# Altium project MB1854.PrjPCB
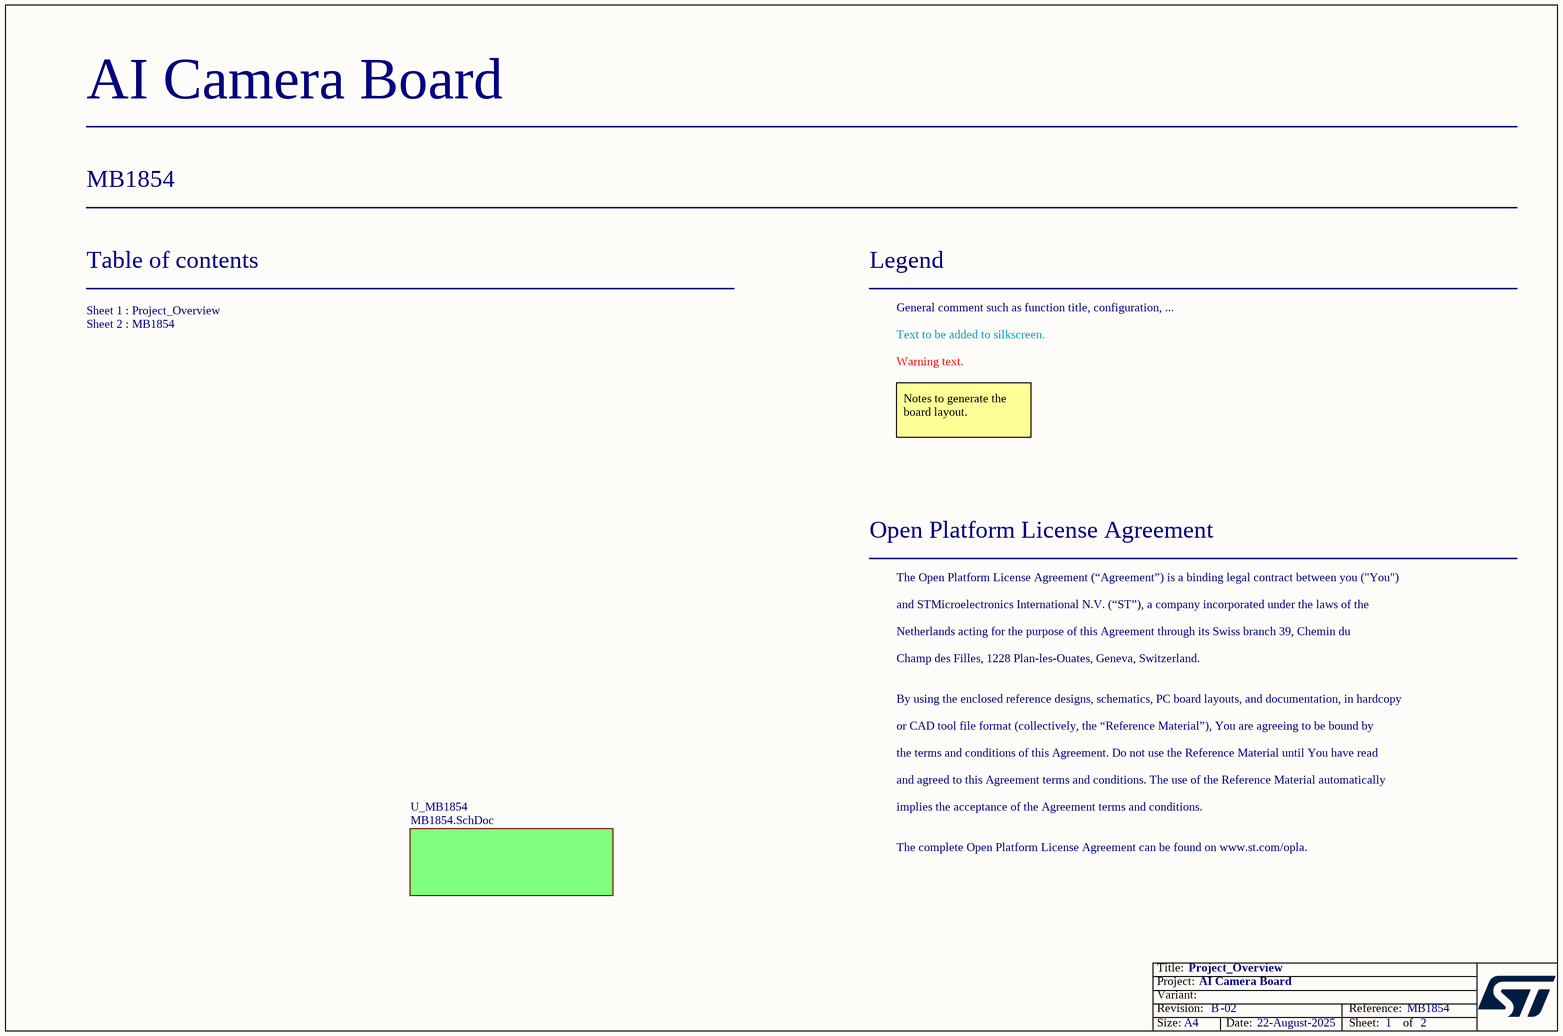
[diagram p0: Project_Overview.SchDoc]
Board_Assembly_Revision: 02; Board_Document_Date: 22-August-2025; Board_Name: AI Camera Board; Board_PCB_Revision: B; Board_Reference: MB1854
2 sheets, 45 parts. Net scope: global (net labels, ports and power ports of the same name join across sheets).
Board file: MB1854.PcbDoc
Sheets:
  Project_Overview.SchDoc
    U_MB1854 = MB1854.SchDoc

## Sheet Project_Overview.SchDoc: Project_Overview
size A4; Date: Not used; ApprovedBy: Not used; CheckedBy: Not used; Author: Not used; CompanyName: STMicroelectronics; DrawnBy: Not used; Engineer: Not used; Organization: Not used; Address1: Not used; Address2: Not used; Address3: Not used; Address4: Not used; DocumentNumber: 1; Revision: Not used; SheetNumber: 1; SheetTotal: 2

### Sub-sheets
U_MB1854 = MB1854.SchDoc: no entries

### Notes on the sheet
- Table of contents
- Legend
- General comment such as function title, configuration, ...
- Sheet 1 : Project_Overview
  Sheet 2 : MB1854
- Text to be added to silkscreen.
- Warning text.
- Notes to generate the board layout.
- Open Platform License Agreement
- The Open Platform License Agreement (“Agreement”) is a binding legal contract between you ("You")
- and STMicroelectronics International N.V. (“ST”), a company incorporated under the laws of the
- Netherlands acting for the purpose of this Agreement through its Swiss branch 39, Chemin du
- Champ des Filles, 1228 Plan-les-Ouates, Geneva, Switzerland.
- By using the enclosed reference designs, schematics, PC board layouts, and documentation, in hardcopy
- or CAD tool file format (collectively, the “Reference Material”), You are agreeing to be bound by
- the terms and conditions of this Agreement. Do not use the Reference Material until You have read
- and agreed to this Agreement terms and conditions. The use of the Reference Material automatically
- implies the acceptance of the Agreement terms and conditions.
- The complete Open Platform License Agreement can be found on www.st.com/opla.

## Sheet MB1854.SchDoc: MB1854
size A3; Date: Not used; ApprovedBy: Not used; CheckedBy: Not used; Author: Not used; CompanyName: STMicroelectronics; DrawnBy: Not used; Engineer: Not used; Organization: Not used; Address1: Not used; Address2: Not used; Address3: Not used; Address4: Not used; DocumentNumber: Not used; Revision: Not used; SheetNumber: 2; SheetTotal: 2
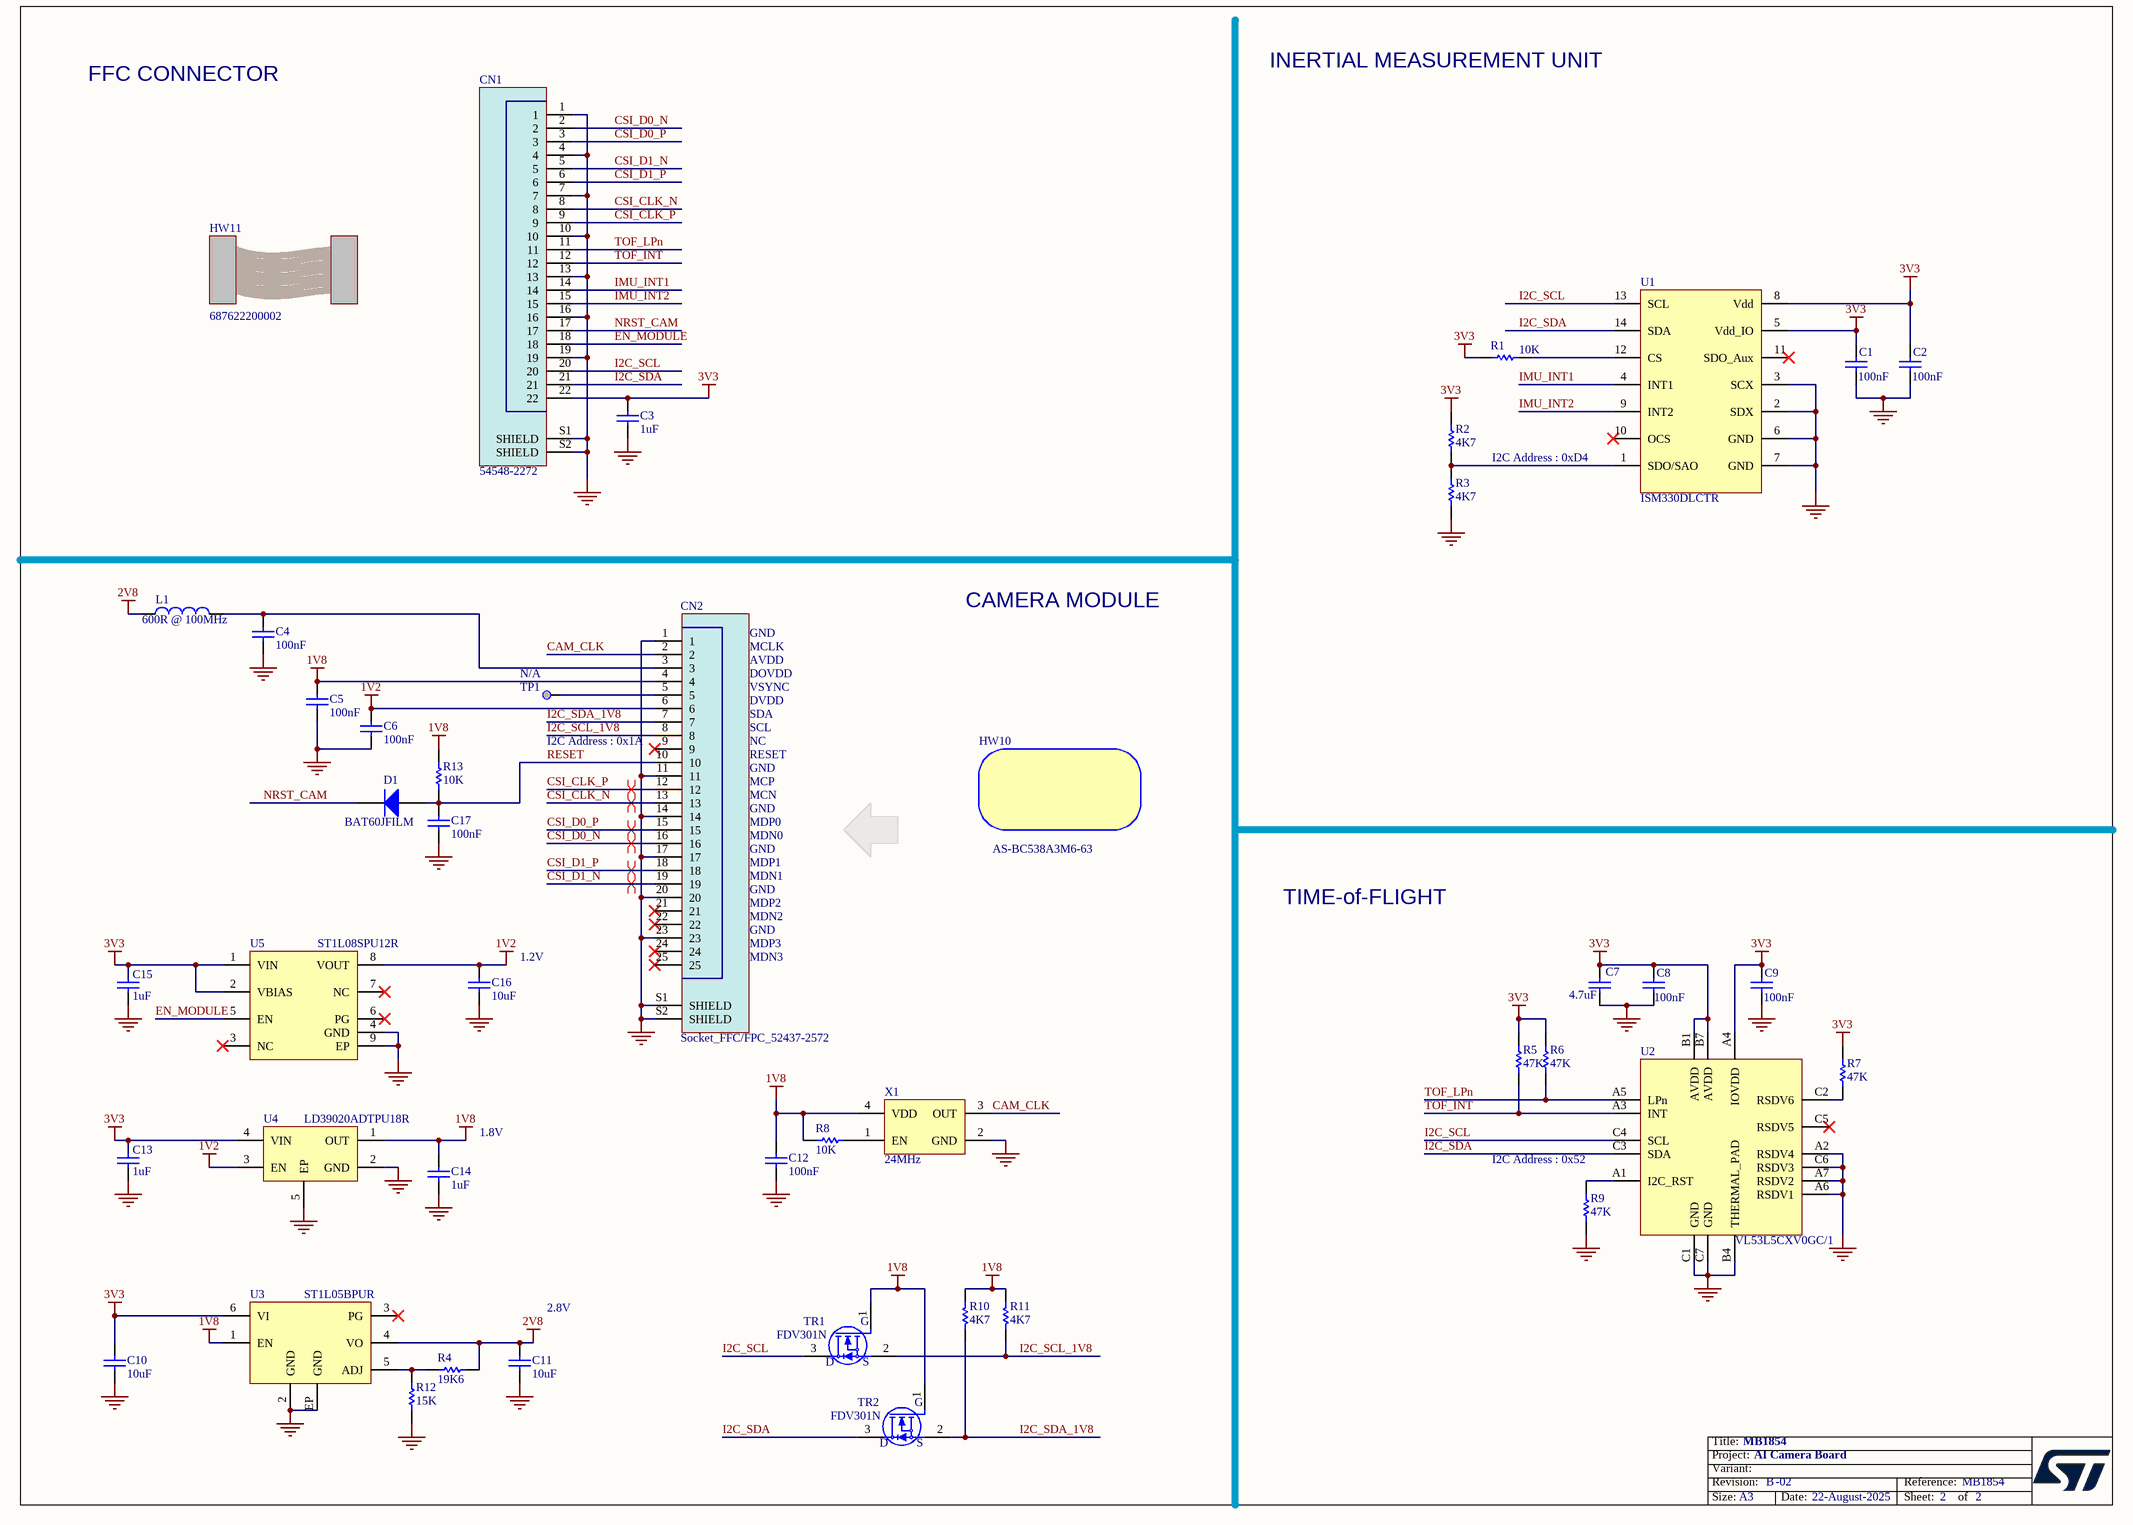
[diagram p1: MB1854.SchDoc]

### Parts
C1  value 100nF  [C0603]  (hidden comment: Capacitor)
C2  value 100nF  [C0603]  (hidden comment: Capacitor)
C3  value 1uF  [C0402]  (hidden comment: Capacitor)
C4  value 100nF  [C0603]  (hidden comment: Capacitor)
C5  value 100nF  [C0603]  (hidden comment: Capacitor)
C6  value 100nF  [C0603]  (hidden comment: Capacitor)
C7  value 4.7uF  [C0603]  (hidden comment: Capacitor)
C8  value 100nF  [C0603]  (hidden comment: Capacitor)
C9  value 100nF  [C0603]  (hidden comment: Capacitor)
C10  value 10uF  [C0402]  (hidden comment: Capacitor)
C11  value 10uF  [C0402]  (hidden comment: Capacitor)
C12  value 100nF  [C0603]  (hidden comment: Capacitor)
C13  value 1uF  [C0402]  (hidden comment: Capacitor)
C14  value 1uF  [C0402]  (hidden comment: Capacitor)
C15  value 1uF  [C0402]  (hidden comment: Capacitor)
C16  value 10uF  [C0402]  (hidden comment: Capacitor)
C17  value 100nF  [C0603]  (hidden comment: Capacitor)
CN1  value 54548-2272  [CON_MOLEX_54548-2271]  (hidden comment: CON_54548-227x)
CN2  value Socket_FFC/FPC_52437-2572  [CON_MOLEX_52437-2533]  (hidden comment: CON_5243725xx)
D1  BAT60JFILM  [DIO_SOD323]
HW10  value AS-BC538A3M6-63  [CAM_DRAWING_AS-BC538A3M6-63]  (hidden comment: Camera_Module)
HW11  value 687622200002  (hidden comment: CABLE)  (no BOM)
L1  value 600R @ 100MHz  [L0603]  (hidden comment: BEAD)
R1  value 10K  [R0402]  (hidden comment: Resistor)
R2  value 4K7  [R0402]
R3  value 4K7  [R0402]
R4  value 19K6  [R0402]  (hidden comment: Resistor)
R5  value 47K  [R0402]  (hidden comment: Resistor)
R6  value 47K  [R0402]  (hidden comment: Resistor)
R7  value 47K  [R0402]  (hidden comment: Resistor)
R8  value 10K  [R0402]  (hidden comment: Resistor)
R9  value 47K  [R0402]  (hidden comment: Resistor)
R10  value 4K7  [R0402]  (hidden comment: Resistor)
R11  value 4K7  [R0402]  (hidden comment: Resistor)
R12  value 15K  [R0402]  (hidden comment: Resistor)
R13  value 10K  [R0402]  (hidden comment: Resistor)
TP1  Test Point  [TP_SMD_1MM]  (value not drawn)  (no BOM)
TR1  value FDV301N  [MOS_SOT23]  (hidden comment: BSN20)
TR2  value FDV301N  [MOS_SOT23]  (hidden comment: BSN20)
U1  ISM330DLCTR  [ICC_LGA14_3X2P5_P050]
U2  VL53L5CXV0GC/1  [ICC_LGA16_6P4X3_P075_H1P5]
U3  ST1L05BPUR  [ICC_DFN6-EPAD_3X3_P095]
U4  value LD39020ADTPU18R  [REG_XDFN4-EPAD_CASE-711AJ_1X1_H0P4_P065]  (hidden comment: LD39020)
U5  ST1L08SPU12R  [ICC_DFN8-EPAD_2X3_P050_H0P9]
X1  value 24MHz  [OSC_NDK_NZ2520SB_4P]  (hidden comment: OSCILLATOR_4_PINS)

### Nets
1V2: C6.1 C16.2 CN2.6 U4.3(EN) U5.8(VOUT)
1V8: C5.1 C12.2 C14.2 CN2.4 R8.1 R10.2 R11.2 R13.1 TR1.1(G) TR2.1(G) U3.1(EN) U4.1(OUT) X1.4(VDD)
2V8: C11.2 L1.1 R4.2 U3.4(VO)
3V3: C1.2 C2.2 C3.2 C7.2 C8.2 C9.2 C10.2 C13.2 C15.2 CN1.22 R1.2 R2.2 R5.2 R6.2 R7.2 U1.5(Vdd_IO) U1.8(Vdd) U2.A4(IOVDD) U2.B1(AVDD) U2.B7(AVDD) U3.6(VI) U4.4(VIN) U5.1(VIN) U5.2(VBIAS)
GND: C1.1 C2.1 C3.1 C4.2 C5.2 C6.2 C7.1 C8.1 C9.1 C10.1 C11.1 C12.1 C13.1 C14.1 C15.1 C16.1 C17.2 CN1.1 CN1.4 CN1.7 CN1.10 CN1.13 CN1.16 CN1.19 CN1.S1(SHIELD) CN1.S2(SHIELD) CN2.1 CN2.11 CN2.14 CN2.17 CN2.20 CN2.23 CN2.S1(SHIELD) CN2.S2(SHIELD) R3.1 R9.1 R12.1 U1.2(SDX) U1.3(SCX) U1.6(GND) U1.7(GND) U2.A2(RSDV4) U2.A6(RSDV1) U2.A7(RSDV2) U2.B4(THERMAL_PAD) U2.C1(GND) U2.C6(RSDV3) U2.C7(GND) U3.2(GND) U3.EP(GND) U4.2(GND) U4.5(EP) U5.4(GND) U5.9(EP) X1.2(GND)
CAM_CLK: CN2.2 X1.3(OUT)
CSI_CLK_N: CN1.8 CN2.13
CSI_CLK_P: CN1.9 CN2.12
CSI_D0_N: CN1.2 CN2.16
CSI_D0_P: CN1.3 CN2.15
CSI_D1_N: CN1.5 CN2.19
CSI_D1_P: CN1.6 CN2.18
EN_MODULE: CN1.18 U5.5(EN)
I2C_SCL: CN1.20 TR1.3(D) U1.13(SCL) U2.C4(SCL)
I2C_SCL_1V8: CN2.8 R11.1 TR1.2(S)
I2C_SDA: CN1.21 TR2.3(D) U1.14(SDA) U2.C3(SDA)
I2C_SDA_1V8: CN2.7 R10.1 TR2.2(S)
IMU_INT1: CN1.14 U1.4(INT1)
IMU_INT2: CN1.15 U1.9(INT2)
NRST_CAM: CN1.17 D1.2(K)
RESET: C17.1 CN2.10 D1.1(A) R13.2
TOF_INT: CN1.12 R5.1 U2.A3(INT)
TOF_LPn: CN1.11 R6.1 U2.A5(LPn)
NetC4_1: C4.1 CN2.3 L1.2
NetCN2_5: CN2.5 TP1.1
NetR1_1: R1.1 U1.12(CS)
NetR2_1: R2.1 R3.2 U1.1(SDO/SAO)
NetR4_1: R4.1 R12.2 U3.5(ADJ)
NetR7_1: R7.1 U2.C2(RSDV6)
NetR8_2: R8.2 X1.1(EN)
NetR9_2: R9.2 U2.A1(I2C_RST)

Not connected (* = marked no-connect by the designer): CN2 9* 21* 22* 24* 25*; U1 10(OCS)* 11(SDO_Aux)*; U2 C5(RSDV5)*; U3 3(PG)*; U5 3(NC)* 6(PG)* 7(NC)*

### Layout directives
differential pair: CSI_CLK_N, CSI_CLK_P, CSI_D0_N, CSI_D0_P, CSI_D1_N, CSI_D1_P

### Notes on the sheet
- FFC CONNECTOR
- INERTIAL MEASUREMENT UNIT
- I2C Address : 0xD4
- MCLK
- GND
- CAMERA MODULE
- AVDD
- DOVDD
- VSYNC
- DVDD
- SDA
- I2C Address : 0x1A
- SCL
- RESET
- MCP
- NC
- MCN
- MDP0
- MDN0
- MDP1
- MDN1
- MDP2
- MDN2
- TIME-of-FLIGHT
- (near C16) 1.2V
- MDP3
- MDN3
- (near C14) 1.8V
- I2C Address : 0x52
- (near C11) 2.8V

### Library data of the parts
C1 C2 C4-C6 C8 C9 C12 C17 = MCD-00211: Capacitor, MLCC, 100nF, 16V, X7R, 10%, 0603, T=0,8mm; Manufacturer_Part_Number: CC0603KRX7R7BB104; Manufacturer: YAGEO; Part_Preference: Recommended; Partial_Alternate_Internal_Part_Number: MCD-01099; Provided_By: SUBCO; Initial_Board_Reference: MB1319; Component_Country_Of_Origin: China; ID: 2659; Order_Code_RS: 669-8763; ShowFields: YES
C3 = MCD-00095: Capacitor, MLCC, 1uF, 25V, X5R, +/-10%, 0402, T=0,5mm; Manufacturer_Part_Number: GRM155R61E105KA12; Manufacturer: MURATA; Part_Preference: Recommended; Alternate_Manufacturer_Part_Number: GRM155R60J105KE19; Partial_Alternate_Internal_Part_Number: MCD-04188; Order_Code_RS: 2218855; Component_Country_Of_Origin: Japan°°; ID: 2772; ShowFields: YES
C7 = MCD-00009: Capacitor, MLCC, 4.7uF, 16V, X5R, +/-10%, 0603, T=0.8mm; Part_Preference: Recommended; Manufacturer: YAGEO; Manufacturer_Part_Number: CC0603KRX5R7BB475; Partial_Alternate_Internal_Part_Number: MCD-03565; Component_Country_Of_Origin: China; ID: 2471; ShowFields: YES; Alternate_EMS: A
C10 C11 C16 = MCD-01532: Capacitor, MLCC, 10uF, 10V, X5R, +/-20%, 0402, T=0.5mm; Part_Preference: Recommended; Manufacturer: MURATA; Manufacturer_Part_Number: GRM155R61A106ME11; Component_Country_Of_Origin: Japan°°; ShowFields: YES; ID: 3632
C13-C15 = MCD-00095: Capacitor, MLCC, 1uF, 25V, X5R, +/-10%, 0402, T=0,5mm; Manufacturer_Part_Number: GRM155R61E105KA12; Manufacturer: MURATA; Alternate_Manufacturer_Part_Number: GRM155R60J105KE19; Part_Preference: Recommended; Partial_Alternate_Internal_Part_Number: MCD-04188; Order_Code_RS: 2218855; Component_Country_Of_Origin: Japan°°; ID: 2772; ShowFields: YES
CN1 = MCD-03311: Socket_FFC/FPC, 22pins, 0.5mm, RA, SMD, T=1.2mm; Part_Type: Connector; Part_Preference: Recommended; Manufacturer: MOLEX; ID: 5427; ShowFields: YES; Component_Country_Of_Origin: China
CN2 = MCD-04565: Socket_FFC/FPC, 25pins, 0.5mm, RA, SMD, T=2mm; Part_Type: Connector; Part_Preference: Recommended; Manufacturer: MOLEX; Manufacturer_Part_Number: 52437-2572; Partial_Alternate_Internal_Part_Number: MCD-04649; ShowFields: YES; ID: 6681; Component_Country_Of_Origin: Unknown
D1 = MCD-00034: BMS_Part_Number: 9151097; Part_Type: Diode; Part_Preference: Recommended; Manufacturer: STMICROELECTRONICS; Manufacturer_HQ_COO: EU; Component_Country_Of_Origin: China; ShowFields: YES; ID: 2483; Order_Code_RS: 714-6879
HW10 = MCD-02783: Camera Module, Dual lane CSI 5MP raw, with IMX335 sensor; Part_Type: Misc; Part_Preference: Recommended; Manufacturer: HONGJIA; ShowFields: YES; ID: 4895; Component_Country_Of_Origin: China
HW11 = MCD-02903: FFC/FPC Flex Cable, Same Side Contacts, WR-FFC 0.5mm, Type1, 22P, 200mm length; Part_Type: Accessory; Part_Preference: Recommended; Manufacturer: WURTH ELEKTRONIK; Order_Code_RS: 163-1631; ShowFields: YES; ID: 5019; Component_Country_Of_Origin: China
L1 = MCD-00047: SMD Chip ferrite bead, 600R@100MHz +/-25%, 350mA, 500mohm DC, 0603, T=0.8mm; Part_Type: Inductor; Manufacturer_Part_Number: FCM1608KF-601T03; Manufacturer: TAI-TECH; Part_Preference: Recommended; Partial_Alternate_Internal_Part_Number: MCD-02959; Provided_By: SUBCO; Initial_Board_Reference: MB1274; Component_Country_Of_Origin: Unknown; ID: 2546; ShowFields: YES
R1 R8 R13 = MCD-00053: Resistor, 10K, 0402, +/-1%, 1/16W; BMS_Part_Number: 9131590; Part_Preference: Recommended; Manufacturer: YAGEO; Manufacturer_Part_Number: RC0402FR-0710KL; Order_Code_RS: 9239359; Component_Country_Of_Origin: China; ID: 2539; ShowFields: YES
R2 R3 = MCD-00065: Resistor,4K7,0402,1%,1/16W; Manufacturer_Part_Number: RC0402FR-074K7L; Manufacturer: YAGEO; Alternate_Manufacturer_Part_Number: RT0402FRE074K7L; Part_Preference: Recommended; Partial_Alternate_Internal_Part_Number: MCD-03300; Provided_By: SUBCO; Initial_Board_Reference: mb1274; Order_Code_RS: 9239316; Component_Country_Of_Origin: China; ID: 2526; ShowFields: YES
R4 = MCD-00344: Resistor, 19K6, 0402, +/-1%, 1/16W; Part_Preference: Recommended; Manufacturer: YAGEO; Manufacturer_Part_Number: RC0402FR-0719K6L; Component_Country_Of_Origin: China; ShowFields: YES; ID: 2937
R5-R7 R9 = MCD-00063: Resistor, 47K, 0402, +/-1%, 1/16W; Part_Preference: Recommended; Manufacturer: YAGEO; Manufacturer_Part_Number: RC0402FR-0747KL; Order_Code_RS: 9239430; Component_Country_Of_Origin: China; ID: 2528; ShowFields: YES
R10 R11 = MCD-00065: Resistor,4K7,0402,1%,1/16W; Part_Preference: Recommended; Manufacturer: YAGEO; Manufacturer_Part_Number: RC0402FR-074K7L; Alternate_Manufacturer_Part_Number: RT0402FRE074K7L; Partial_Alternate_Internal_Part_Number: MCD-03300; Order_Code_RS: 9239316; Component_Country_Of_Origin: China; ID: 2526; ShowFields: YES
R12 = MCD-01943: Resistor, 15K, 0402, +/-1%, 1/16W; Part_Preference: Recommended; Manufacturer: YAGEO; Manufacturer_Part_Number: RC0402FR-0715KL; Order_Code_RS: 618-6009; Component_Country_Of_Origin: China; ShowFields: YES; ID: 4043
TP1 = MCD-00074: Test Point 1mm; Part_Type: Misc; Part_Preference: Recommended; ShowFields: YES; ID: 2518; Component_Country_Of_Origin: Unknown
TR1 TR2 = MCD-02156: MOSFET, N-Channel , Vds: 25V, Id: 0,22A, Vgs(th): 1.06V, Vgs(max): +/-8V, Rdson:5ohm@Vgs=2.7V, Qg=0,49nC; Part_Type: Transistor; Part_Preference: Recommended; Manufacturer: ON SEMICONDUCTOR; Component_Country_Of_Origin: China°°; ID: 4256; ShowFields: YES
U1 = MCD-01714: iNEMO inertial module: 3D accelerometer and 3D gyroscope, with digital output for industrial applications; Part_Type: IC; Part_Preference: Recommended; Manufacturer: STMICROELECTRONICS; Manufacturer_HQ_COO: EU; Component_Country_Of_Origin: Philippines; ID: 3814; ShowFields: YES; Order_Code_RS: 162-3602
U2 = MCD-02590: Sensor, Time-of-Flight 8x8 multizone ranging, with wide field of view; Part_Type: IC; Part_Preference: Recommended; Manufacturer: STMICROELECTRONICS; ShowFields: YES; ID: 4696; Component_Country_Of_Origin: China
U3 = MCD-00581: LDO Linear Voltage Regulator IC Positive Adjustable 1 Output Adjustable 1.3A 6-DFN (3x3); BMS_Part_Number: 9176239; Part_Preference: Recommended; Manufacturer: STMICROELECTRONICS; Manufacturer_HQ_COO: EU; Component_Country_Of_Origin: Malaysia; ShowFields: YES; ID: 3163; Order_Code_RS: 188-9209
U4 = MCD-02224: LDO, output 1V8, 200 mA very low quiescent current; Part_Preference: Recommended; Part_Type: IC; Manufacturer: STMICROELECTRONICS; Manufacturer_HQ_COO: EU; Component_Country_Of_Origin: China; ID: 4324; ShowFields: YES
U5 = MCD-02920: LDO, fixe 1V2, Input 1V to 5.5V, 0.8A; Part_Type: IC; Part_Preference: Recommended; Manufacturer: STMICROELECTRONICS; ShowFields: YES; ID: 5036; Component_Country_Of_Origin: China
X1 = MCD-01976: Oscillator, SPXO, 24Mhz, +/-50ppm, 3V3, square wave, 2.5x2mm; Part_Type: Crystal_Osc; Part_Preference: Recommended; Manufacturer: NDK; Manufacturer_Part_Number: NZ2520SH-24MHZ-END4869D; Component_Country_Of_Origin: Japan; ID: 4076; ShowFields: YES

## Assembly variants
CSI: not fitted R2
